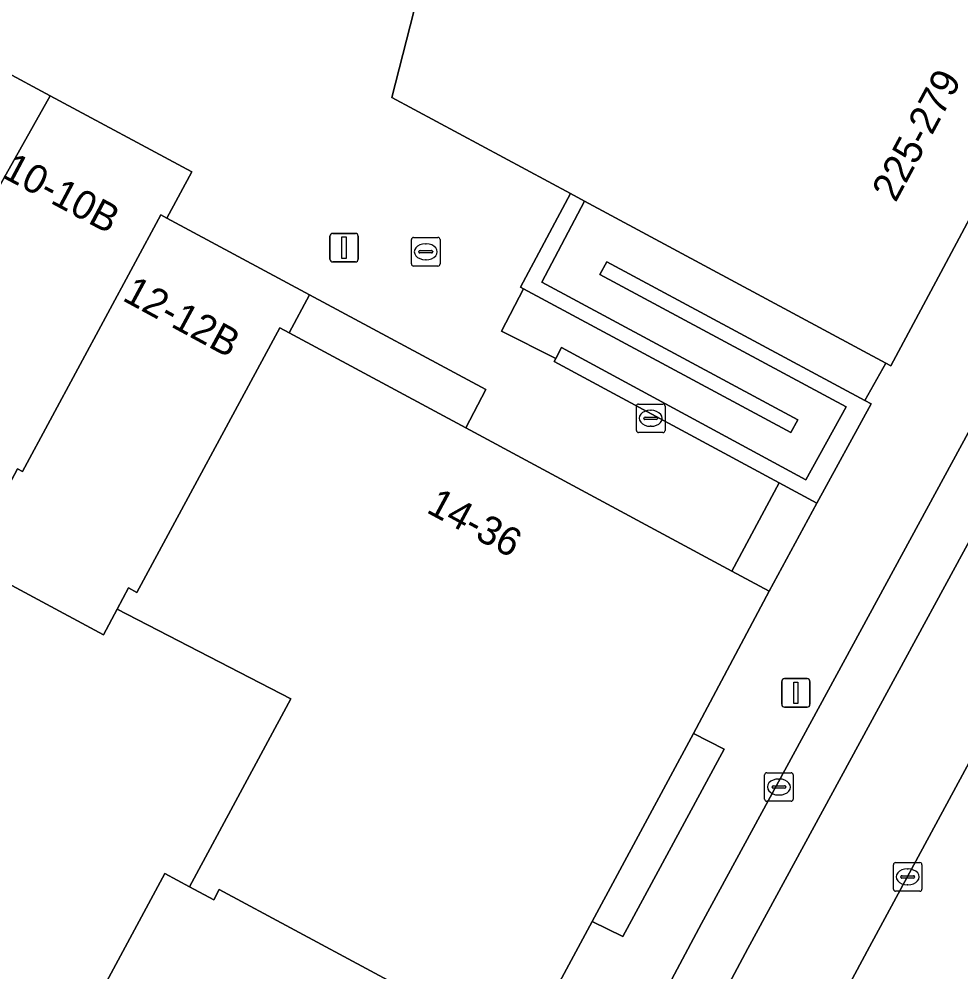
# Model space of a CAD drawing. Extents: x 159489 to 160304, y 383825 to 384531.
# Drawn here: x 159796.11 to 159829.08, y 384059.86 to 384093.22 of the extents above; entities that cross this region are included whole.
import ezdxf

# ---------------------------------------------------------------- set-up
doc = ezdxf.new("R2010")
doc.units = 0
for name, color, linetype in [('IMGEO_Berm_groen', 7, 'Continuous'), ('IMGEO_Erf', 7, 'Continuous'), ('IMGEO_Kolk', 7, 'Continuous'), ('IMGEO_Lichtmast', 7, 'Continuous'), ('IMGEO_Muur', 7, 'Continuous'), ('IMGEO_Pand', 7, 'Continuous'), ('IMGEO_Pand_nummerreeks', 7, 'Continuous'), ('IMGEO_Pand_overbouw', 7, 'Continuous'), ('IMGEO_Parkeervlak_gesloten', 7, 'Continuous'), ('IMGEO_Rijbaan_lokaal_gesloten', 7, 'Continuous'), ('IMGEO_Voetpad_gesloten', 7, 'Continuous'), ('IMGEO_Voetpad_open', 7, 'Continuous')]:
    doc.layers.add(name, color=color, linetype=linetype)

msp = doc.modelspace()

# ---------------------------------------------------------------- linework, layer by layer
at = {"layer": 'IMGEO_Berm_groen'}
msp.add_lwpolyline([(159844.928, 384088.249), (159841.694, 384089.989), (159825.877, 384060.739), (159803.412, 384018.855), (159803.036, 384018.159), (159806.279, 384016.403), (159815.461, 384033.388), (159819.297, 384040.613)], close=True, dxfattribs=at)
at = {"layer": 'IMGEO_Erf'}
msp.add_lwpolyline([(159798.849, 384058.909), (159801.215, 384063.308), (159802.082, 384062.843), (159805.621, 384069.422), (159799.545, 384072.565), (159799.063, 384071.666), (159794.306, 384074.223), (159795.238, 384075.958), (159790.453, 384078.53), (159785.726, 384081.072), (159786.545, 384082.595), (159787.322, 384084.039), (159782.746, 384086.499), (159778.243, 384088.92), (159772.986, 384091.747), (159773.584, 384092.86), (159771.882, 384093.775), (159768.398, 384087.297)], dxfattribs=at)
at = {"layer": 'IMGEO_Kolk'}
for p, q in [((159809.847, 384084.65), (159809.847, 384085.502)), ((159809.922, 384085.576), (159810.774, 384085.576)), ((159810.335, 384085.356), (159810.36, 384085.356)), ((159810.848, 384085.502), (159810.848, 384084.65)), ((159810.106, 384085.07), (159810.106, 384085.082)), ((159810.544, 384085.033), (159810.146, 384085.033)), ((159810.149, 384085.119), (159810.547, 384085.119)), ((159810.59, 384085.082), (159810.59, 384085.07)), ((159810.358, 384084.796), (159810.333, 384084.796)), ((159810.774, 384084.576), (159809.922, 384084.576)), ((159817.721, 384078.819), (159817.721, 384079.671)), ((159817.796, 384079.745), (159818.648, 384079.745)), ((159818.722, 384079.671), (159818.722, 384078.819)), ((159818.209, 384079.525), (159818.234, 384079.525)), ((159817.98, 384079.239), (159817.98, 384079.251)), ((159818.418, 384079.202), (159818.02, 384079.202)), ((159818.023, 384079.288), (159818.421, 384079.288)), ((159818.464, 384079.251), (159818.464, 384079.239)), ((159818.648, 384078.745), (159817.796, 384078.745)), ((159818.232, 384078.965), (159818.207, 384078.965)), ((159822.209, 384065.911), (159822.209, 384066.763)), ((159822.284, 384066.837), (159823.136, 384066.837)), ((159823.21, 384066.763), (159823.21, 384065.911)), ((159822.468, 384066.331), (159822.468, 384066.343)), ((159822.511, 384066.38), (159822.909, 384066.38)), ((159822.697, 384066.617), (159822.722, 384066.617)), ((159822.952, 384066.343), (159822.952, 384066.331)), ((159822.906, 384066.294), (159822.508, 384066.294)), ((159822.72, 384066.057), (159822.695, 384066.057)), ((159823.136, 384065.837), (159822.284, 384065.837)), ((159826.791, 384063.689), (159827.643, 384063.689)), ((159826.716, 384062.763), (159826.716, 384063.615)), ((159827.204, 384063.469), (159827.229, 384063.469)), ((159827.717, 384063.615), (159827.717, 384062.763)), ((159826.975, 384063.183), (159826.975, 384063.195)), ((159827.413, 384063.146), (159827.015, 384063.146)), ((159827.018, 384063.232), (159827.416, 384063.232)), ((159827.459, 384063.195), (159827.459, 384063.183)), ((159827.643, 384062.689), (159826.791, 384062.689)), ((159827.227, 384062.909), (159827.202, 384062.909))]:
    msp.add_line(p, q, dxfattribs=at)
for points in [[(159809.847, 384084.65), (159809.847, 384085.502)], [(159809.922, 384085.576), (159810.774, 384085.576)], [(159810.848, 384085.502), (159810.848, 384084.65)], [(159810.774, 384084.576), (159809.922, 384084.576)], [(159817.721, 384078.819), (159817.721, 384079.671)], [(159817.796, 384079.745), (159818.648, 384079.745)], [(159818.722, 384079.671), (159818.722, 384078.819)], [(159818.648, 384078.745), (159817.796, 384078.745)], [(159822.209, 384065.911), (159822.209, 384066.763)], [(159822.284, 384066.837), (159823.136, 384066.837)], [(159823.21, 384066.763), (159823.21, 384065.911)], [(159823.136, 384065.837), (159822.284, 384065.837)], [(159826.791, 384063.689), (159827.643, 384063.689)], [(159826.716, 384062.763), (159826.716, 384063.615)], [(159827.717, 384063.615), (159827.717, 384062.763)], [(159827.643, 384062.689), (159826.791, 384062.689)]]:
    msp.add_lwpolyline(points, dxfattribs=at)
for centre, radius, start, end in [((159809.924, 384085.5), 0.0765, 91.552, 178.448), ((159809.924, 384085.5), 0.0765, 91.552, 178.448), ((159810.772, 384085.5), 0.0765, 1.552, 88.448), ((159810.772, 384085.5), 0.0765, 1.552, 88.448), ((159810.146, 384085.079), 0.0403, 85.8775, 175.7526), ((159810.143, 384085.069), 0.0366, 178.938, 274.7102), ((159810.547, 384085.076), 0.043, 264.8664, 352.4533), ((159810.551, 384085.081), 0.0386, 1.7309, 96.639), ((159809.924, 384084.652), 0.0765, 181.552, 268.448), ((159809.924, 384084.652), 0.0765, 181.552, 268.448), ((159810.772, 384084.652), 0.0765, 271.552, 358.448), ((159810.772, 384084.652), 0.0765, 271.552, 358.448), ((159817.798, 384079.669), 0.0765, 91.552, 178.448), ((159817.798, 384079.669), 0.0765, 91.552, 178.448), ((159818.646, 384079.669), 0.0765, 1.552, 88.448), ((159818.646, 384079.669), 0.0765, 1.552, 88.448), ((159818.02, 384079.248), 0.0403, 85.8775, 175.7526), ((159818.017, 384079.238), 0.0366, 178.938, 274.7102), ((159818.421, 384079.245), 0.043, 264.8664, 352.4533), ((159818.425, 384079.25), 0.0386, 1.7309, 96.639), ((159817.798, 384078.821), 0.0765, 181.552, 268.448), ((159817.798, 384078.821), 0.0765, 181.552, 268.448), ((159818.646, 384078.821), 0.0765, 271.552, 358.448), ((159818.646, 384078.821), 0.0765, 271.552, 358.448), ((159822.286, 384066.761), 0.0765, 91.552, 178.448), ((159822.286, 384066.761), 0.0765, 91.552, 178.448), ((159823.134, 384066.761), 0.0765, 1.552, 88.448), ((159823.134, 384066.761), 0.0765, 1.552, 88.448), ((159822.508, 384066.34), 0.0403, 85.8775, 175.7526), ((159822.505, 384066.33), 0.0366, 178.938, 274.7102), ((159822.909, 384066.337), 0.043, 264.8664, 352.4533), ((159822.913, 384066.342), 0.0386, 1.7309, 96.639), ((159822.286, 384065.913), 0.0765, 181.552, 268.448), ((159822.286, 384065.913), 0.0765, 181.552, 268.448), ((159823.134, 384065.913), 0.0765, 271.552, 358.448), ((159823.134, 384065.913), 0.0765, 271.552, 358.448), ((159826.793, 384063.613), 0.0765, 91.552, 178.448), ((159826.793, 384063.613), 0.0765, 91.552, 178.448), ((159827.641, 384063.613), 0.0765, 1.552, 88.448), ((159827.641, 384063.613), 0.0765, 1.552, 88.448), ((159827.015, 384063.192), 0.0403, 85.8775, 175.7526), ((159827.012, 384063.182), 0.0366, 178.938, 274.7102), ((159827.416, 384063.189), 0.043, 264.8664, 352.4533), ((159827.42, 384063.194), 0.0386, 1.7309, 96.639), ((159826.793, 384062.765), 0.0765, 181.552, 268.448), ((159826.793, 384062.765), 0.0765, 181.552, 268.448), ((159827.641, 384062.765), 0.0765, 271.552, 358.448), ((159827.641, 384062.765), 0.0765, 271.552, 358.448)]:
    msp.add_arc(centre, radius, start, end, dxfattribs=at)
for centre, major_axis, ratio, start_param, end_param in [((159810.334, 384085.076), (-0.387, 0.002), 0.722429, 4.712389, 7.853982), ((159810.359, 384085.076), (-0.39, 0.002), 0.717154, 1.570796, 4.712389), ((159818.208, 384079.245), (-0.387, 0.002), 0.722429, 4.712389, 7.853982), ((159818.233, 384079.245), (-0.39, 0.002), 0.717154, 1.570796, 4.712389), ((159822.696, 384066.337), (-0.387, 0.002), 0.722429, 4.712389, 7.853982), ((159822.721, 384066.337), (-0.39, 0.002), 0.717154, 1.570796, 4.712389), ((159827.203, 384063.189), (-0.387, 0.002), 0.722429, 4.712389, 7.853982), ((159827.228, 384063.189), (-0.39, 0.002), 0.717154, 1.570796, 4.712389)]:
    msp.add_ellipse(centre, major_axis=major_axis, ratio=ratio, start_param=start_param, end_param=end_param, dxfattribs=at)
at = {"layer": 'IMGEO_Lichtmast'}
for p, q in [((159807.093, 384085.719), (159807.883, 384085.719)), ((159807.883, 384085.719), (159807.093, 384085.719)), ((159806.993, 384084.819), (159806.993, 384085.619)), ((159806.993, 384085.619), (159806.993, 384084.819)), ((159807.983, 384085.619), (159807.983, 384084.819)), ((159807.983, 384084.819), (159807.983, 384085.619)), ((159807.883, 384084.719), (159807.093, 384084.719)), ((159807.093, 384084.719), (159807.883, 384084.719)), ((159822.807, 384069.232), (159822.807, 384070.032)), ((159822.807, 384070.032), (159822.807, 384069.232)), ((159822.907, 384070.132), (159823.697, 384070.132)), ((159823.697, 384070.132), (159822.907, 384070.132)), ((159823.797, 384070.032), (159823.797, 384069.232)), ((159823.797, 384069.232), (159823.797, 384070.032)), ((159823.697, 384069.132), (159822.907, 384069.132)), ((159822.907, 384069.132), (159823.697, 384069.132))]:
    msp.add_line(p, q, dxfattribs=at)
for points in [[(159807.413, 384085.594), (159807.563, 384085.594), (159807.563, 384084.844), (159807.413, 384084.844), (159807.413, 384085.594)], [(159823.227, 384070.007), (159823.377, 384070.007), (159823.377, 384069.257), (159823.227, 384069.257), (159823.227, 384070.007)]]:
    msp.add_lwpolyline(points, dxfattribs=at)
for centre, start, end in [((159807.093, 384085.619), 90, 180), ((159807.093, 384085.619), 90, 180), ((159807.883, 384085.619), 0, 90), ((159807.883, 384085.619), 360, 90), ((159807.093, 384084.819), 180, 270), ((159807.093, 384084.819), 180, 270), ((159807.883, 384084.819), 270, 0), ((159807.883, 384084.819), 270, 0), ((159822.907, 384070.032), 90, 180), ((159822.907, 384070.032), 90, 180), ((159823.697, 384070.032), 0, 90), ((159823.697, 384070.032), 360, 90), ((159822.907, 384069.232), 180, 270), ((159822.907, 384069.232), 180, 270), ((159823.697, 384069.232), 270, 0), ((159823.697, 384069.232), 270, 0)]:
    msp.add_arc(centre, 0.1, start, end, dxfattribs=at)
at = {"layer": 'IMGEO_Muur'}
for points in [[(159815.417, 384087.11), (159813.666, 384083.835), (159813.766, 384083.773), (159823.128, 384078.749), (159823.369, 384079.191), (159814.409, 384084.008), (159815.906, 384086.847)], [(159824.035, 384076.271), (159825.936, 384079.753), (159825.719, 384079.87), (159816.687, 384084.721), (159816.44, 384084.277), (159825.06, 384079.649), (159823.656, 384077.092), (159815.101, 384081.729), (159814.897, 384081.336), (159814.84, 384081.228), (159822.717, 384076.982)]]:
    msp.add_lwpolyline(points, close=True, dxfattribs=at)
at = {"layer": 'IMGEO_Pand'}
msp.add_lwpolyline([(159829.252, 384099.702), (159828.64, 384101.158), (159829.123, 384101.594), (159829.539, 384102.326), (159830.962, 384107.902), (159814.676, 384112.061), (159809.159, 384090.473), (159815.417, 384087.11), (159815.906, 384086.847), (159826.448, 384081.181), (159826.63, 384081.083), (159828.467, 384084.527), (159834.642, 384096.101), (159833.182, 384096.456), (159833.803, 384098.255), (159831.175, 384099.666)], dxfattribs=at)
for points in [[(159797.202, 384090.532), (159792.249, 384093.193), (159788.25, 384085.766), (159787.322, 384084.039), (159786.545, 384082.595), (159785.726, 384081.072), (159790.453, 384078.53), (159791.301, 384080.038)], [(159801.071, 384086.372), (159801.286, 384086.256), (159802.155, 384087.87), (159797.202, 384090.532), (159791.301, 384080.038), (159790.453, 384078.53), (159795.238, 384075.958), (159796.056, 384077.48), (159796.238, 384077.383)], [(159805.24, 384082.416), (159805.565, 384082.24), (159806.283, 384083.563), (159801.286, 384086.256), (159801.071, 384086.372), (159796.238, 384077.383), (159796.056, 384077.48), (159795.238, 384075.958), (159794.306, 384074.223), (159799.063, 384071.666), (159799.545, 384072.565), (159799.942, 384073.305), (159800.234, 384073.149)], [(159805.565, 384082.24), (159805.24, 384082.416), (159800.234, 384073.149), (159799.942, 384073.305), (159799.545, 384072.565), (159805.621, 384069.422), (159802.082, 384062.843), (159802.928, 384062.389), (159803.121, 384062.744), (159813.711, 384057.051), (159816.172, 384061.629), (159819.714, 384068.212), (159822.364, 384073.19), (159821.062, 384073.891), (159811.752, 384078.907)], [(159803.121, 384062.744), (159802.928, 384062.389), (159802.082, 384062.843), (159801.215, 384063.308), (159798.849, 384058.909), (159800.561, 384057.988), (159811.153, 384052.293), (159813.711, 384057.051)]]:
    msp.add_lwpolyline(points, close=True, dxfattribs=at)
at = {"layer": 'IMGEO_Pand_overbouw'}
for points in [[(159806.283, 384083.563), (159805.565, 384082.24), (159811.752, 384078.907), (159812.447, 384080.257)], [(159816.172, 384061.629), (159817.243, 384061.099), (159820.789, 384067.656), (159819.714, 384068.212)]]:
    msp.add_lwpolyline(points, close=True, dxfattribs=at)
at = {"layer": 'IMGEO_Parkeervlak_gesloten'}
msp.add_lwpolyline([(159833.197, 384085.844), (159819.995, 384061.553), (159809.693, 384042.226), (159811.322, 384041.358), (159821.621, 384060.678), (159834.394, 384084.181), (159834.819, 384084.963)], close=True, dxfattribs=at)
at = {"layer": 'IMGEO_Rijbaan_lokaal_gesloten'}
for points in [[(159805.875, 384031.899), (159804.558, 384032.564), (159803.752, 384031.078), (159805.339, 384030.131), (159802.79, 384025.429), (159801.167, 384026.309), (159799.393, 384023.037), (159797.098, 384018.803), (159801.988, 384016.22), (159803.036, 384018.159), (159803.412, 384018.855), (159825.877, 384060.739), (159841.694, 384089.989)], [(159835.051, 384085.907), (159833.649, 384086.676), (159833.197, 384085.844), (159834.819, 384084.963), (159834.394, 384084.181), (159821.621, 384060.678), (159811.322, 384041.358), (159809.693, 384042.226), (159805.766, 384034.859), (159807.126, 384034.114)]]:
    msp.add_lwpolyline(points, dxfattribs=at)
at = {"layer": 'IMGEO_Voetpad_gesloten'}
msp.add_lwpolyline([(159815.906, 384086.847), (159814.409, 384084.008), (159823.369, 384079.191), (159823.128, 384078.749), (159813.766, 384083.773), (159812.995, 384082.298), (159814.897, 384081.336), (159815.101, 384081.729), (159823.656, 384077.092), (159825.06, 384079.649), (159816.44, 384084.277), (159816.687, 384084.721), (159825.719, 384079.87), (159826.448, 384081.181)], close=True, dxfattribs=at)
at = {"layer": 'IMGEO_Voetpad_open'}
for points in [[(159792.852, 384094.351), (159792.249, 384093.193), (159797.202, 384090.532), (159802.155, 384087.87), (159801.286, 384086.256), (159806.283, 384083.563), (159812.447, 384080.257), (159811.752, 384078.907), (159821.062, 384073.891), (159822.717, 384076.982), (159814.84, 384081.228), (159814.897, 384081.336), (159812.995, 384082.298), (159813.766, 384083.773), (159813.666, 384083.835), (159815.417, 384087.11), (159809.159, 384090.473), (159814.676, 384112.061)], [(159834.642, 384096.101), (159828.467, 384084.527), (159826.63, 384081.083), (159826.448, 384081.181), (159825.719, 384079.87), (159825.936, 384079.753), (159824.035, 384076.271), (159822.364, 384073.19), (159819.714, 384068.212), (159820.789, 384067.656), (159817.243, 384061.099), (159816.172, 384061.629), (159813.711, 384057.051), (159811.153, 384052.293), (159808.594, 384047.531), (159805.871, 384042.465), (159804.812, 384043.02), (159802.47, 384038.666), (159803.527, 384038.097), (159797.928, 384027.689), (159796.313, 384024.693), (159799.393, 384023.037), (159801.167, 384026.309), (159803.752, 384031.078)], [(159807.126, 384034.114), (159805.766, 384034.859), (159809.693, 384042.226), (159819.995, 384061.553), (159833.197, 384085.844), (159833.649, 384086.676), (159835.051, 384085.907)]]:
    msp.add_lwpolyline(points, dxfattribs=at)
for points in [[(159811.752, 384078.907), (159812.447, 384080.257), (159806.283, 384083.563), (159805.565, 384082.24)], [(159822.717, 384076.982), (159821.062, 384073.891), (159822.364, 384073.19), (159824.035, 384076.271)], [(159820.789, 384067.656), (159819.714, 384068.212), (159816.172, 384061.629), (159817.243, 384061.099)]]:
    msp.add_lwpolyline(points, close=True, dxfattribs=at)

# ---------------------------------------------------------------- texts
at = {"layer": 'IMGEO_Pand_nummerreeks'}
for s, rotation, p in [('225-279', 61.7069, (159826.795, 384086.773)), ('10-10B', 331.9824, (159795.467, 384087.709)), ('12-12B', 331.5756, (159799.689, 384083.393)), ('14-36', 331.6233, (159810.332, 384075.97))]:
    msp.add_text(s, height=1, rotation=rotation, dxfattribs=at).set_placement(p)

doc.saveas('drawing.dxf')
